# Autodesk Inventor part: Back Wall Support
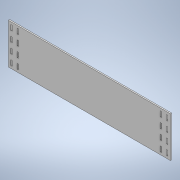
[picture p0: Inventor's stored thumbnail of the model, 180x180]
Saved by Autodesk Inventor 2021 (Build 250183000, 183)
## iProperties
Created: 2026-10
Part Number: Back Wall Support
Material: Generic
Document SubType Name: Modeling
Designer: hp
Density: 1 g/cm^3
Appearance: Default
Author: hp
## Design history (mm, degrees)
sketch "Sketch1"
  geometry: L1 (0, 160)-(640, 160); L2 (640, 160)-(640, 0); L3 (640, 0)-(0, 0); L4 (0, 0)-(0, 160); L5 (320, 160)-(320, 0); L6 (10, 150)-(15, 150); L7 (15, 150)-(15, 130); L8 (15, 130)-(10, 130); L9 (10, 130)-(10, 150); L10 (10, 110)-(15, 110); L11 (15, 110)-(15, 90); L12 (15, 90)-(10, 90); L13 (10, 90)-(10, 110); L14 (10, 70)-(15, 70); L15 (15, 70)-(15, 50); L16 (15, 50)-(10, 50); L17 (10, 50)-(10, 70); L18 (10, 30)-(15, 30); L19 (15, 30)-(15, 10); L20 (15, 10)-(10, 10); L21 (10, 10)-(10, 30); L22 (35, 150)-(40, 150); L23 (40, 150)-(40, 130); L24 (40, 130)-(35, 130); L25 (35, 130)-(35, 150); L26 (35, 110)-(40, 110); L27 (40, 110)-(40, 90); L28 (40, 90)-(35, 90); L29 (35, 90)-(35, 110); L30 (35, 70)-(40, 70); L31 (40, 70)-(40, 50); L32 (40, 50)-(35, 50); L33 (35, 50)-(35, 70); L34 (35, 30)-(40, 30); L35 (40, 30)-(40, 10); L36 (40, 10)-(35, 10); L37 (35, 10)-(35, 30); L38 (630, 110)-(625, 110); L39 (605, 110)-(600, 110); L40 (630, 90)-(630, 110); L41 (625, 90)-(630, 90); L42 (625, 110)-(625, 90); L43 (600, 90)-(605, 90); L44 (600, 110)-(600, 90); L45 (605, 90)-(605, 110); L46 (630, 70)-(625, 70); L47 (630, 50)-(630, 70); L48 (625, 70)-(625, 50); L49 (605, 50)-(605, 70); L50 (600, 70)-(600, 50); L51 (605, 70)-(600, 70); L52 (600, 50)-(605, 50); L53 (605, 30)-(600, 30); L54 (630, 30)-(625, 30); L55 (600, 30)-(600, 10); L56 (600, 10)-(605, 10); L57 (605, 10)-(605, 30); L58 (625, 30)-(625, 10); L59 (625, 10)-(630, 10); L60 (630, 10)-(630, 30); L61 (625, 50)-(630, 50); L62 (600, 130)-(605, 130); L63 (625, 130)-(630, 130); L64 (605, 150)-(600, 150)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; 15 further points
  constraints: 138 end point, 39 symmetric about line, 4 parallel, 3 horizontal, 2 collinear, 2 midpoint, 2 perpendicular, 1 coincident, 1 vertical, 61 other
  dimensions: "d15" = 640 distance of L2.end L3.end; "d36" = 160 distance between parallel lines of L3 L1; "d51" = 5 distance of L7.end L8.end; "d52" = 20 distance of L6.end L7.end; "d53" = 10 distance between parallel lines of L1 L6; "d54" = 10 distance between parallel lines of L4 L9; "d57" = 40 distance of L1.start point (0, 120); "d60" = 25 distance of L1.start point (25, 160)
extrude "Extrusion1" new body sketch "Sketch1" distance "d34" = 5; taper "d35" = 0 deg
body "Solid1"
